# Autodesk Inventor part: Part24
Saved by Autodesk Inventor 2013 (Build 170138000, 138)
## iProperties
Created: 2012-07
Part Number: Part24
Material: Steel
Document SubType Name: Modeling
Designer: Paul
Density: 1 g/cm^3
Author: Paul
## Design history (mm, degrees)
node "User Library-Arduino Mega.SAT1"
body "Solid1"
node "Base1"
